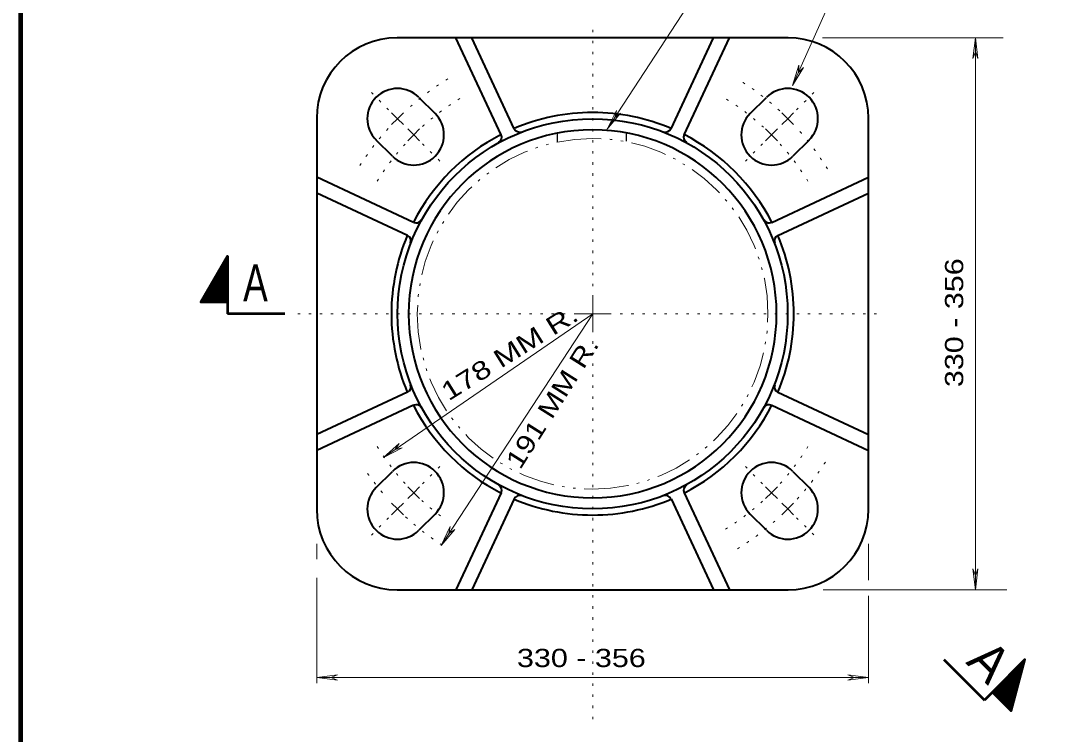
# Model space of a CAD drawing. Extents: x 312583 to 312854, y 144419 to 144597.
# Drawn here: x 312616.5 to 312659.66, y 144538.66 to 144568.4 of the extents above; entities that cross this region are included whole.
import ezdxf
from ezdxf.enums import TextEntityAlignment as Align

# ---------------------------------------------------------------- set-up
doc = ezdxf.new("R2010")
doc.units = 0
doc.header["$LTSCALE"] = 0.3
for name, pattern in [('DASH_DOUBLE_DOT', [9.2, 5, -1.2, 0.3, -1.2, 0.3, -1.2]), ('DOTTED', [1.5, 0.3, -1.2]), ('SHORT_DASHED', [2.7, 1.5, -1.2])]:
    doc.linetypes.add(name, pattern=pattern)
doc.layers.add('1', color=7, linetype='Continuous', lineweight=40)
doc.layers.add('2', color=7, linetype='Continuous', lineweight=13)

msp = doc.modelspace()

# ---------------------------------------------------------------- linework, layer by layer
at = {"layer": '1'}
for p, q in [((312640.3356, 144567.6863), (312632.1859, 144567.6863)), ((312636.5253, 144563.6383), (312634.6393, 144567.6863)), ((312637.0696, 144563.8913), (312635.3063, 144567.6863)), ((312648.4776, 144567.6863), (312640.3356, 144567.6863)), ((312643.6016, 144563.8913), (312645.3649, 144567.6863)), ((312644.1459, 144563.6383), (312646.0319, 144567.6863)), ((312633.0906, 144565.2023), (312633.7729, 144564.5276)), ((312646.8983, 144564.5276), (312647.5806, 144565.2023)), ((312628.8356, 144564.3283), (312628.8356, 144548.0366)), ((312651.8356, 144548.0366), (312651.8356, 144564.3283)), ((312631.9943, 144562.749), (312631.3119, 144563.4236)), ((312649.3593, 144563.4236), (312648.6769, 144562.749)), ((312632.8759, 144559.989), (312628.8356, 144561.875)), ((312647.7953, 144559.989), (312651.8356, 144561.875)), ((312632.6229, 144559.4446), (312628.8356, 144561.2156)), ((312648.0483, 144559.4446), (312651.8356, 144561.2156)), ((312632.6229, 144552.9203), (312628.8356, 144551.1493)), ((312648.0483, 144552.9203), (312651.8356, 144551.1493)), ((312632.8759, 144552.376), (312628.8356, 144550.49)), ((312647.7953, 144552.376), (312651.8356, 144550.49)), ((312631.3119, 144548.9413), (312631.9943, 144549.616)), ((312648.6769, 144549.616), (312649.3593, 144548.9413)), ((312636.5253, 144548.7266), (312634.6393, 144544.6863)), ((312637.0696, 144548.4736), (312635.3063, 144544.6863)), ((312643.6016, 144548.4736), (312645.3649, 144544.6863)), ((312644.1459, 144548.7266), (312646.0319, 144544.6863)), ((312633.7729, 144547.8373), (312633.0906, 144547.1626)), ((312647.5806, 144547.1626), (312646.8983, 144547.8373)), ((312632.1859, 144544.6863), (312640.3356, 144544.6863)), ((312640.3356, 144544.6863), (312648.4776, 144544.6863))]:
    msp.add_line(p, q, dxfattribs=at)
at = {"layer": '1', "lineweight": 158}
msp.add_lwpolyline([(312616.5, 144423.1446), (312616.5, 144585.0846), (312849, 144585.0846)], dxfattribs=at)
at = {"layer": '1'}
msp.add_circle((312640.3337, 144556.1825), 8.1278, dxfattribs=at)
for centre, radius, start, end in [((312632.1878, 144564.3283), 3.3542, 90, 180), ((312648.4795, 144564.3283), 3.3542, 0, 90), ((312632.2013, 144564.3149), 1.2578, 45, 225), ((312648.4661, 144564.3149), 1.2578, 315, 135), ((312632.8798, 144563.6364), 1.2578, 225, 45), ((312640.3337, 144556.1825), 8.3854, 90, 112.94673), ((312640.3337, 144556.1825), 8.3854, 67.05327, 90), ((312647.7876, 144563.6364), 1.2578, 135, 315), ((312640.3337, 144556.1825), 7.6667, 90, 180), ((312640.3337, 144556.1825), 8.3854, 117.05705, 152.95096), ((312636.3083, 144563.5385), 0.2396, 298.68804, 25.01264), ((312637.2867, 144563.9947), 0.2396, 205.00333, 291.30722), ((312640.3337, 144556.1825), 7.6667, 0, 90), ((312643.3807, 144563.9947), 0.2396, 248.69278, 334.99667), ((312644.359, 144563.5385), 0.2396, 154.98736, 241.31196), ((312640.3337, 144556.1825), 8.3854, 27.05705, 62.95096), ((312632.9776, 144560.2078), 0.2396, 244.98736, 331.31196), ((312647.6898, 144560.2078), 0.2396, 208.68804, 295.01264), ((312640.3337, 144556.1825), 8.3854, 157.05327, 180), ((312632.5214, 144559.2295), 0.2396, 338.69278, 64.99667), ((312648.1459, 144559.2295), 0.2396, 115.00333, 201.30722), ((312640.3337, 144556.1825), 8.3854, 0, 22.94673), ((312640.3337, 144556.1825), 8.3854, 180, 202.94673), ((312640.3331, 144556.1819), 7.6667, 180, 270), ((312640.3337, 144556.1825), 7.6667, 270, 0), ((312640.3337, 144556.1825), 8.3854, 337.05327, 0), ((312632.5214, 144553.1355), 0.2396, 295.00333, 21.30722), ((312648.1459, 144553.1355), 0.2396, 158.69278, 244.99667), ((312640.3337, 144556.1825), 8.3854, 207.05705, 242.95096), ((312632.9776, 144552.1571), 0.2396, 28.68804, 115.01264), ((312640.3337, 144556.1825), 8.3854, 297.05705, 332.95096), ((312647.6898, 144552.1571), 0.2396, 64.98736, 151.31196), ((312632.8798, 144548.7285), 1.2578, 315, 135), ((312647.7876, 144548.7285), 1.2578, 45, 225), ((312632.2013, 144548.0501), 1.2578, 135, 315), ((312636.3083, 144548.8264), 0.2396, 334.98736, 61.31196), ((312644.359, 144548.8264), 0.2396, 118.68804, 205.01264), ((312648.4661, 144548.0501), 1.2578, 225, 45), ((312640.3337, 144556.1825), 8.3854, 247.05327, 270), ((312637.2867, 144548.3702), 0.2396, 68.69278, 154.99667), ((312640.3337, 144556.1825), 8.3854, 270, 292.94673), ((312643.3807, 144548.3702), 0.2396, 25.00333, 111.30722), ((312632.1878, 144548.0366), 3.3542, 180, 270), ((312648.4795, 144548.0366), 3.3542, 270, 0)]:
    msp.add_arc(centre, radius, start, end, dxfattribs=at)
at = {"layer": '1', "linetype": 'DOTTED', "lineweight": 13}
for radius, start, end in [(11.5, 121.67302, 132.67646), (11.5, 47.32354, 58.32698), (10.5417, 121.67021, 132.50277), (10.5417, 47.49723, 58.32979), (11.5, 137.83702, 148.35019), (11.5, 31.64981, 42.16298), (10.5417, 137.83921, 148.35431), (10.5417, 31.64569, 42.16079), (10.5417, 211.64569, 222.16079), (10.5417, 317.83921, 328.35431), (11.5, 317.83702, 328.35019), (11.5, 215.3347, 222.16255), (10.5417, 227.49787, 233.37708), (10.5417, 301.67021, 312.50277), (11.5, 227.32354, 238.32698), (11.5, 301.67302, 312.67646)]:
    msp.add_arc((312640.3337, 144556.1825), radius, start, end, dxfattribs=at)
at = {"layer": '1', "linetype": 'DASH_DOUBLE_DOT', "lineweight": 13}
for start, end in [(90, 180), (0, 90), (180, 270), (270, 0)]:
    msp.add_arc((312640.3337, 144556.1825), 7.3073, start, end, dxfattribs=at)
at = {"layer": '2'}
for p, q in [((312646.0243, 144571.696), (312640.9413, 144563.876)), ((312649.9189, 144567.6863), (312657.4476, 144567.6863)), ((312656.2841, 144567.6863), (312656.1768, 144566.82)), ((312656.2841, 144567.6863), (312656.3914, 144566.82)), ((312656.1768, 144566.82), (312656.2841, 144567.096)), ((312656.3914, 144566.82), (312656.2841, 144567.096)), ((312648.6693, 144565.7006), (312648.9299, 144566.5363)), ((312648.9299, 144566.5363), (312648.9146, 144566.2373)), ((312648.6693, 144565.7006), (312649.1216, 144566.452)), ((312649.1216, 144566.452), (312648.9146, 144566.2373)), ((312632.2013, 144564.313), (312631.9559, 144564.5583)), ((312632.2013, 144564.313), (312632.4466, 144564.5583)), ((312640.9413, 144563.876), (312641.3246, 144564.658)), ((312640.9413, 144563.876), (312641.5009, 144564.543)), ((312641.3246, 144564.658), (312641.2633, 144564.3666)), ((312641.5009, 144564.543), (312641.2633, 144564.3666)), ((312648.4699, 144564.313), (312648.2246, 144564.5583)), ((312648.4699, 144564.313), (312648.7076, 144564.5583)), ((312632.2013, 144564.313), (312631.9559, 144564.0753)), ((312632.2013, 144564.313), (312632.4466, 144564.0753)), ((312648.4699, 144564.313), (312648.2246, 144564.0753)), ((312648.4699, 144564.313), (312648.7076, 144564.0753)), ((312632.8836, 144563.6383), (312632.6383, 144563.8836)), ((312632.8836, 144563.6383), (312632.6383, 144563.393)), ((312632.8836, 144563.6383), (312633.1213, 144563.8836)), ((312632.8836, 144563.6383), (312633.1213, 144563.393)), ((312647.7876, 144563.6383), (312647.5423, 144563.8836)), ((312647.7876, 144563.6383), (312647.5423, 144563.393)), ((312647.7876, 144563.6383), (312648.0329, 144563.8836)), ((312647.7876, 144563.6383), (312648.0329, 144563.393)), ((312640.3356, 144556.1863), (312640.3356, 144556.953)), ((312640.3356, 144556.1863), (312640.3356, 144556.953)), ((312640.3356, 144556.1863), (312631.6186, 144550.1986)), ((312640.3356, 144556.1863), (312639.5689, 144556.1863)), ((312640.3356, 144556.1863), (312641.1023, 144556.1863)), ((312640.3356, 144556.1863), (312640.3356, 144555.4196)), ((312631.6186, 144550.1986), (312632.2703, 144550.7736)), ((312631.6186, 144550.1986), (312632.2703, 144550.7736)), ((312631.6186, 144550.1986), (312632.3929, 144550.5973)), ((312631.6186, 144550.1986), (312632.3929, 144550.5973)), ((312632.2703, 144550.7736), (312632.1093, 144550.5283)), ((312632.2703, 144550.7736), (312632.1093, 144550.5283)), ((312632.3929, 144550.5973), (312632.1093, 144550.5283)), ((312632.3929, 144550.5973), (312632.1093, 144550.5283)), ((312632.8836, 144548.7266), (312632.6383, 144548.972)), ((312632.8836, 144548.7266), (312632.6383, 144548.972)), ((312632.8836, 144548.7266), (312633.1213, 144548.972)), ((312647.7876, 144548.7266), (312647.5423, 144548.972)), ((312647.7876, 144548.7266), (312648.0329, 144548.972)), ((312632.8836, 144548.7266), (312632.6383, 144548.489)), ((312632.8836, 144548.7266), (312633.1213, 144548.489)), ((312647.7876, 144548.7266), (312647.5423, 144548.489)), ((312647.7876, 144548.7266), (312648.0329, 144548.489)), ((312632.2013, 144548.052), (312631.9559, 144548.2973)), ((312632.2013, 144548.052), (312631.9559, 144548.2973)), ((312632.2013, 144548.052), (312631.9559, 144547.8066)), ((312632.2013, 144548.052), (312632.4466, 144548.2973)), ((312632.2013, 144548.052), (312632.4466, 144547.8066)), ((312648.4699, 144548.052), (312648.2246, 144548.2973)), ((312648.4699, 144548.052), (312648.2246, 144547.8066)), ((312648.4699, 144548.052), (312648.7076, 144548.2973)), ((312648.4699, 144548.052), (312648.7076, 144547.8066)), ((312634.0183, 144546.534), (312634.4016, 144547.316)), ((312634.0183, 144546.534), (312634.5856, 144547.201)), ((312634.4016, 144547.316), (312634.3403, 144547.0246)), ((312634.5856, 144547.201), (312634.3403, 144547.0246)), ((312628.8356, 144546.603), (312628.8356, 144545.959)), ((312651.8356, 144546.603), (312651.8356, 144545.0773)), ((312656.1768, 144545.5526), (312656.2841, 144545.2766)), ((312656.2841, 144544.6863), (312656.1768, 144545.5526)), ((312656.3914, 144545.5526), (312656.2841, 144545.2766)), ((312656.2841, 144544.6863), (312656.3914, 144545.5526)), ((312628.8356, 144545.177), (312628.8356, 144540.7916)), ((312649.9419, 144544.6863), (312657.5912, 144544.6863)), ((312651.8356, 144544.4256), (312651.8356, 144540.7916)), ((312628.8356, 144541.0293), (312629.7019, 144541.1366)), ((312628.8356, 144541.0293), (312651.8356, 144541.0293)), ((312628.8356, 144541.0293), (312629.7019, 144540.922)), ((312629.7019, 144541.1366), (312629.4259, 144541.0293)), ((312629.7019, 144540.922), (312629.4259, 144541.0293)), ((312650.9693, 144541.1366), (312651.2453, 144541.0293)), ((312651.8356, 144541.0293), (312650.9693, 144541.1366)), ((312650.9693, 144540.922), (312651.2453, 144541.0293)), ((312651.8356, 144541.0293), (312650.9693, 144540.922))]:
    msp.add_line(p, q, dxfattribs=at)
at = {"layer": '2', "linetype": 'DOTTED'}
for p, q in [((312640.3356, 144557.3363), (312640.3356, 144568.3533)), ((312631.8333, 144564.681), (312631.0666, 144565.4553)), ((312648.8303, 144564.681), (312649.6046, 144565.4553)), ((312633.2439, 144563.2703), (312634.1103, 144562.404)), ((312647.4196, 144563.2703), (312646.5609, 144562.404)), ((312639.1856, 144556.1863), (312627.9616, 144556.1863)), ((312641.4856, 144556.1863), (312652.4949, 144556.1863)), ((312640.3356, 144555.0363), (312640.3356, 144538.9746)), ((312633.2439, 144549.0946), (312634.1103, 144549.961)), ((312647.4196, 144549.0946), (312646.5609, 144549.961)), ((312631.8333, 144547.684), (312631.0666, 144546.9173)), ((312648.8303, 144547.684), (312649.6046, 144546.9173))]:
    msp.add_line(p, q, dxfattribs=at)
at = {"layer": '2', "linetype": 'SHORT_DASHED', "lineweight": 25}
for p, q in [((312638.8713, 144563.347), (312638.8713, 144563.7303)), ((312641.7463, 144563.37), (312641.7463, 144563.7073))]:
    msp.add_line(p, q, dxfattribs=at)
at = {"layer": '2', "lineweight": 35}
for p, q in [((312625.1173, 144558.2026), (312624.9486, 144558.2946)), ((312625.1173, 144558.2333), (312624.9639, 144558.3176)), ((312625.1173, 144558.2563), (312624.9793, 144558.333)), ((312625.1173, 144558.287), (312624.9869, 144558.356)), ((312625.1173, 144558.31), (312625.0023, 144558.379)), ((312625.1173, 144558.333), (312625.0099, 144558.402)), ((312625.1173, 144558.3636), (312625.0253, 144558.4173)), ((312625.1173, 144558.3943), (312625.0329, 144558.4403)), ((312625.1173, 144558.425), (312625.0483, 144558.4633)), ((312625.1173, 144558.448), (312625.0559, 144558.4786)), ((312625.1173, 144558.4786), (312625.0713, 144558.5016)), ((312625.1173, 144558.5016), (312625.0789, 144558.5246)), ((312625.1173, 144558.5323), (312625.0943, 144558.54)), ((312625.1173, 144558.563), (312625.1019, 144558.563)), ((312625.1173, 144557.643), (312624.7109, 144557.8806)), ((312625.1173, 144557.6736), (312624.7186, 144557.9036)), ((312625.1173, 144557.7043), (312624.7339, 144557.919)), ((312625.1173, 144557.735), (312624.7493, 144557.942)), ((312625.1173, 144557.758), (312624.7569, 144557.965)), ((312625.1173, 144557.7886), (312624.7723, 144557.9803)), ((312625.1173, 144557.8116), (312624.7876, 144558.0033)), ((312625.1173, 144557.8423), (312624.7953, 144558.0263)), ((312625.1173, 144557.8653), (312624.8106, 144558.0416)), ((312625.1173, 144557.896), (312624.8183, 144558.0646)), ((312625.1173, 144557.9266), (312624.8336, 144558.0876)), ((312625.1173, 144557.9496), (312624.8413, 144558.103)), ((312625.1173, 144557.9803), (312624.8566, 144558.1336)), ((312625.1173, 144558.0033), (312624.8643, 144558.149)), ((312625.1173, 144558.034), (312624.8796, 144558.172)), ((312625.1173, 144558.0646), (312624.8873, 144558.195)), ((312625.1173, 144558.0876), (312624.9026, 144558.2103)), ((312625.1173, 144558.1183), (312624.9103, 144558.2333)), ((312625.1173, 144558.1413), (312624.9256, 144558.2563)), ((312625.1173, 144558.172), (312624.9409, 144558.2716)), ((312625.1096, 144557.068), (312624.4656, 144557.4436)), ((312625.1173, 144557.0986), (312624.4733, 144557.4666)), ((312625.1173, 144557.1216), (312624.4886, 144557.482)), ((312625.1173, 144557.1446), (312624.4963, 144557.505)), ((312625.1173, 144557.1753), (312624.5116, 144557.528)), ((312625.1173, 144557.206), (312624.5193, 144557.5433)), ((312625.1173, 144557.2366), (312624.5346, 144557.5663)), ((312625.1173, 144557.2596), (312624.5423, 144557.5893)), ((312625.1173, 144557.2903), (312624.5576, 144557.6046)), ((312625.1096, 144557.3133), (312624.5653, 144557.6353)), ((312625.1173, 144557.344), (312624.5806, 144557.6506)), ((312625.1173, 144557.367), (312624.5959, 144557.6736)), ((312625.1173, 144557.3976), (312624.6036, 144557.6966)), ((312625.1173, 144557.4283), (312624.6189, 144557.712)), ((312625.1173, 144557.4513), (312624.6266, 144557.735)), ((312625.1173, 144557.482), (312624.6419, 144557.758)), ((312625.1173, 144557.5126), (312624.6496, 144557.7733)), ((312625.1173, 144557.5356), (312624.6649, 144557.7963)), ((312625.1173, 144557.5663), (312624.6726, 144557.8193)), ((312625.1173, 144557.597), (312624.6879, 144557.8346)), ((312625.1173, 144557.62), (312624.6956, 144557.8576)), ((312624.8106, 144556.6616), (312624.2126, 144557.0066)), ((312624.8566, 144556.6616), (312624.2203, 144557.0296)), ((312624.9026, 144556.6616), (312624.2356, 144557.045)), ((312624.9486, 144556.6616), (312624.2509, 144557.068)), ((312625.0023, 144556.6616), (312624.2586, 144557.091)), ((312625.0406, 144556.6616), (312624.2739, 144557.1063)), ((312625.0943, 144556.6616), (312624.2816, 144557.137)), ((312625.1173, 144556.677), (312624.2969, 144557.1523)), ((312625.1173, 144556.7076), (312624.3046, 144557.1753)), ((312625.1173, 144556.7383), (312624.3199, 144557.1983)), ((312625.1173, 144556.7613), (312624.3276, 144557.2136)), ((312625.1173, 144556.792), (312624.3429, 144557.2366)), ((312625.1096, 144556.815), (312624.3506, 144557.2596)), ((312625.1096, 144556.8456), (312624.3659, 144557.275)), ((312625.1173, 144556.8686), (312624.3736, 144557.298)), ((312625.1173, 144556.8993), (312624.3889, 144557.321)), ((312625.1173, 144556.93), (312624.4043, 144557.3363)), ((312625.1173, 144556.953), (312624.4119, 144557.3593)), ((312625.1173, 144556.9836), (312624.4273, 144557.3823)), ((312625.1173, 144557.0143), (312624.4426, 144557.4053)), ((312625.1173, 144557.0373), (312624.4503, 144557.4206)), ((312624.0363, 144556.6616), (312624.0209, 144556.677)), ((312624.0823, 144556.6616), (312624.0286, 144556.7)), ((312624.1359, 144556.6616), (312624.0439, 144556.7153)), ((312624.1819, 144556.6616), (312624.0593, 144556.7383)), ((312624.2356, 144556.6616), (312624.0669, 144556.7613)), ((312624.2739, 144556.6616), (312624.0823, 144556.7766)), ((312624.3276, 144556.6616), (312624.0899, 144556.7996)), ((312624.3736, 144556.6616), (312624.1053, 144556.8226)), ((312624.4196, 144556.6616), (312624.1129, 144556.838)), ((312624.4656, 144556.6616), (312624.1283, 144556.8686)), ((312624.5193, 144556.6616), (312624.1359, 144556.884)), ((312624.5653, 144556.6616), (312624.1513, 144556.907)), ((312624.6113, 144556.6616), (312624.1589, 144556.93)), ((312624.6649, 144556.6616), (312624.1743, 144556.9453)), ((312624.7109, 144556.6616), (312624.1819, 144556.9683)), ((312624.7569, 144556.6616), (312624.1973, 144556.9836)), ((312658.0379, 144541.4663), (312658.2603, 144541.4126)), ((312658.0609, 144541.4893), (312658.2603, 144541.4356)), ((312658.0839, 144541.5123), (312658.2679, 144541.4586)), ((312658.1069, 144541.5353), (312658.2756, 144541.4816)), ((312658.1223, 144541.5506), (312658.2756, 144541.5046)), ((312658.1453, 144541.5736), (312658.2833, 144541.5276)), ((312658.1606, 144541.589), (312658.2909, 144541.5506)), ((312658.1759, 144541.6043), (312658.2986, 144541.5736)), ((312658.1989, 144541.6273), (312658.2986, 144541.5966)), ((312658.2219, 144541.6426), (312658.3139, 144541.6196)), ((312658.2449, 144541.6656), (312658.3139, 144541.6426)), ((312658.2603, 144541.681), (312658.3216, 144541.6656)), ((312658.2756, 144541.704), (312658.3293, 144541.6886)), ((312658.2986, 144541.7193), (312658.3369, 144541.7116)), ((312658.3139, 144541.7423), (312658.3369, 144541.7346)), ((312658.3369, 144541.7653), (312658.3523, 144541.7576)), ((312657.6163, 144541.037), (312658.1146, 144540.9066)), ((312657.6316, 144541.06), (312658.1299, 144540.922)), ((312657.6546, 144541.083), (312658.1299, 144540.945)), ((312657.6699, 144541.0983), (312658.1376, 144540.968)), ((312657.6853, 144541.1136), (312658.1453, 144540.9986)), ((312657.7083, 144541.1366), (312658.1529, 144541.014)), ((312657.7313, 144541.1596), (312658.1529, 144541.037)), ((312657.7543, 144541.1826), (312658.1606, 144541.0676)), ((312657.7696, 144541.198), (312658.1683, 144541.0906)), ((312657.7926, 144541.221), (312658.1683, 144541.106)), ((312657.8079, 144541.2363), (312658.1759, 144541.1366)), ((312657.8309, 144541.2593), (312658.1836, 144541.1596)), ((312657.8463, 144541.2746), (312658.1836, 144541.1826)), ((312657.8693, 144541.2976), (312658.1989, 144541.198)), ((312657.8923, 144541.313), (312658.2066, 144541.2286)), ((312657.9076, 144541.3283), (312658.2066, 144541.244)), ((312657.9306, 144541.3513), (312658.2219, 144541.2746)), ((312657.9459, 144541.3666), (312658.2219, 144541.2976)), ((312657.9613, 144541.3896), (312658.2296, 144541.3206)), ((312657.9843, 144541.4126), (312658.2449, 144541.3436)), ((312657.9996, 144541.428), (312658.2449, 144541.3666)), ((312658.0226, 144541.451), (312658.2526, 144541.3896)), ((312657.1869, 144540.6076), (312657.9766, 144540.393)), ((312657.2023, 144540.6306), (312657.9843, 144540.416)), ((312657.2253, 144540.646), (312657.9919, 144540.4466)), ((312657.2406, 144540.669), (312657.9996, 144540.4696)), ((312657.2636, 144540.6843), (312657.9996, 144540.485)), ((312657.2866, 144540.6996), (312658.0073, 144540.5156)), ((312657.3019, 144540.7303), (312658.0226, 144540.5386)), ((312657.3173, 144540.7456), (312658.0226, 144540.554)), ((312657.3326, 144540.761), (312658.0303, 144540.577)), ((312657.3556, 144540.784), (312658.0379, 144540.6076)), ((312657.3786, 144540.807), (312658.0379, 144540.623)), ((312657.4016, 144540.83), (312658.0456, 144540.646)), ((312657.4169, 144540.8453), (312658.0609, 144540.669)), ((312657.4399, 144540.8683), (312658.0609, 144540.692)), ((312657.4629, 144540.876), (312658.0763, 144540.7226)), ((312657.4783, 144540.9066), (312658.0763, 144540.738)), ((312657.4936, 144540.922), (312658.0763, 144540.7686)), ((312657.5166, 144540.945), (312658.0916, 144540.7916)), ((312657.5396, 144540.9603), (312658.0916, 144540.8146)), ((312657.5549, 144540.9833), (312658.0993, 144540.83)), ((312657.5779, 144540.9986), (312658.1069, 144540.8606)), ((312657.5933, 144541.0216), (312658.1146, 144540.876)), ((312657.0029, 144540.4313), (312657.9229, 144540.186)), ((312657.0106, 144540.4083), (312657.9229, 144540.163)), ((312657.0259, 144540.4543), (312657.9306, 144540.209)), ((312657.0489, 144540.4773), (312657.9383, 144540.2396)), ((312657.0489, 144540.37), (312657.9076, 144540.14)), ((312657.0643, 144540.4926), (312657.9459, 144540.255)), ((312657.0796, 144540.3393), (312657.9076, 144540.117)), ((312657.0873, 144540.5156), (312657.9459, 144540.278)), ((312657.1103, 144540.5233), (312657.9613, 144540.301)), ((312657.1103, 144540.301), (312657.8923, 144540.094)), ((312657.1333, 144540.5463), (312657.9613, 144540.324)), ((312657.1409, 144540.5693), (312657.9689, 144540.347)), ((312657.1486, 144540.2703), (312657.8923, 144540.071)), ((312657.1639, 144540.5923), (312657.9766, 144540.37)), ((312657.1793, 144540.2396), (312657.8923, 144540.048)), ((312657.2099, 144540.2013), (312657.8769, 144540.025)), ((312657.2483, 144540.163), (312657.8693, 144540.002)), ((312657.2789, 144540.1323), (312657.8693, 144539.979)), ((312657.3173, 144540.1016), (312657.8616, 144539.956)), ((312657.3556, 144540.0633), (312657.8616, 144539.933)), ((312657.3863, 144540.0326), (312657.8539, 144539.91)), ((312657.4169, 144540.002), (312657.8463, 144539.887)), ((312657.4553, 144539.9636), (312657.8386, 144539.8716)), ((312657.4859, 144539.9253), (312657.8309, 144539.8333)), ((312657.5166, 144539.8946), (312657.8233, 144539.818)), ((312657.5549, 144539.864), (312657.8156, 144539.795)), ((312657.5933, 144539.8256), (312657.8079, 144539.772)), ((312657.6163, 144539.795), (312657.8079, 144539.749)), ((312657.6546, 144539.7566), (312657.8003, 144539.726)), ((312657.6853, 144539.726), (312657.7926, 144539.703)), ((312657.7236, 144539.6876), (312657.7926, 144539.68)), ((312657.7619, 144539.657), (312657.7773, 144539.657))]:
    msp.add_line(p, q, dxfattribs=at)
at = {"layer": '2', "lineweight": 53}
for p, q in [((312625.1173, 144556.6616), (312625.1173, 144556.1863)), ((312627.5093, 144556.1863), (312625.1173, 144556.1863)), ((312654.9636, 144541.773), (312656.6579, 144540.0863)), ((312656.9953, 144540.4236), (312656.6579, 144540.0863))]:
    msp.add_line(p, q, dxfattribs=at)
at = {"layer": '2'}
for points in [[(312648.6693, 144565.7006), (312650.9923, 144570.914), (312651.4753, 144570.914)], [(312656.2841, 144544.6863), (312656.2841, 144561.783), (312656.2841, 144567.6863)], [(312640.3356, 144556.1863), (312634.0183, 144546.534), (312634.0183, 144546.5723)]]:
    msp.add_lwpolyline(points, dxfattribs=at)
at = {"layer": '2', "lineweight": 53}
for points in [[(312625.1173, 144556.6616), (312624.0056, 144556.6616), (312625.1173, 144558.5783)], [(312656.9953, 144540.4236), (312657.7773, 144539.634), (312658.3523, 144541.773)]]:
    msp.add_lwpolyline(points, close=True, dxfattribs=at)

# ---------------------------------------------------------------- texts
at = {"layer": '2'}
for s, rotation, width, p in [('330 - 356', 90, 1.25, (312655.7778, 144553.1272)), ('178 MM R.', 32, 1.3, (312634.3299, 144552.53)), ('191 MM R.', 57.722, 1.25, (312637.3129, 144549.6544))]:
    msp.add_text(s, height=0.76, rotation=rotation, dxfattribs=dict(at, width=width)).set_placement(p)
at = {"layer": '2', "width": 0.75}
msp.add_text('A', height=1.533, dxfattribs=at).set_placement((312626.2826, 144556.7076), align=Align.CENTER)
at = {"layer": '2', "width": 1.25}
msp.add_text('330 - 356', height=0.76, dxfattribs=at).set_placement((312637.181, 144541.4626))
at = {"layer": '2'}
msp.add_text('A', height=1.533, rotation=315, dxfattribs=at).set_placement((312656.3332, 144541.1547), align=Align.CENTER)

doc.saveas('drawing.dxf')
